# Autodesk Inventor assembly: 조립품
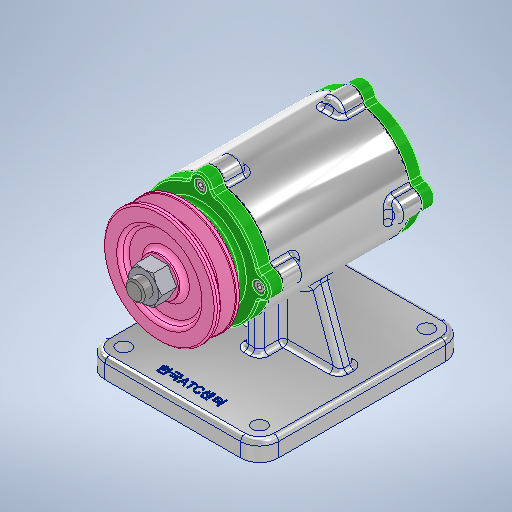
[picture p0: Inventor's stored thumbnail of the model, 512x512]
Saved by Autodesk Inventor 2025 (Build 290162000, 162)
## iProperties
Created: 2024-08
Part Number: 조립품
Document SubType Name: Assembly
Designer: 학생
Author: 학생
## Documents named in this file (12)
- C:\Users\학생\Desktop\740807V1011\조립품.iam
- C:\Users\학생\Desktop\740807V1011\본체.ipt
- C:\Users\학생\Desktop\740807V1011\Ű 4 x 4\Ű 4 x 4.ipt
- C:\Users\학생\Desktop\740807V1011\V-벨트풀리\V-벨트풀리.ipt
- C:\Users\학생\Desktop\740807V1011\개스킷\개스킷.ipt
- C:\Users\학생\Desktop\740807V1011\너트 M12 x 1.25\너트 M12 x 1.25.ipt
- C:\Users\학생\Desktop\740807V1011\뒤커버\뒤커버.ipt
- C:\Users\학생\Desktop\740807V1011\베어링 6204\베어링 6204.ipt
- C:\Users\학생\Desktop\740807V1011\볼트 M4 x 12\볼트 M4 x 12.ipt
- C:\Users\학생\Desktop\740807V1011\앞커버\앞커버.ipt
- C:\Users\학생\Desktop\740807V1011\오일실\오일실.ipt
- C:\Users\학생\Desktop\740807V1011\축\축.ipt
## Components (4 placed, 3 different names)
1. Ű 4 x 4:1 — 각도:1, 각도:2, 각도:3, 각도:4
2. V-벨트풀리:1
3. 개스킷:1
4. 개스킷:2
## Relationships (4: Angle 4)
- 각도:1 [Angle]: Ű 4 x 4:1
- 각도:2 [Angle]: Ű 4 x 4:1
- 각도:3 [Angle]: Ű 4 x 4:1
- 각도:4 [Angle]: Ű 4 x 4:1
